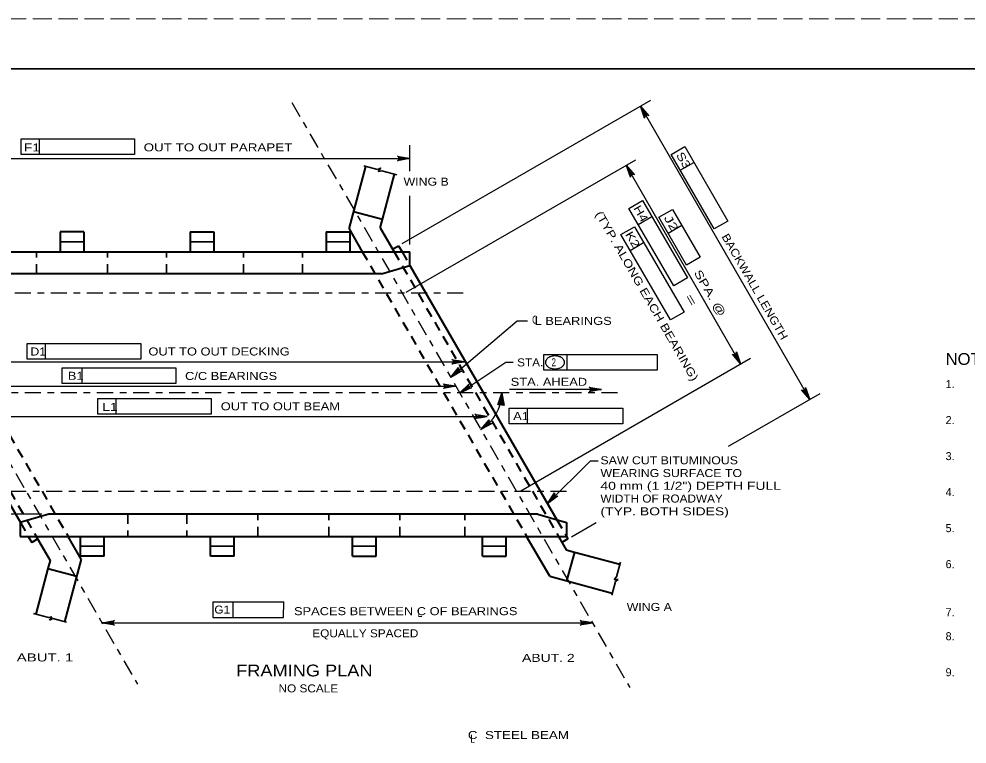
# Model space of a CAD drawing. Extents: x -11 to 79, y -154 to 0.
# Drawn here: x 43.06 to 57.27, y -10.87 to 0 of the extents above; entities that cross this region are included whole.
import ezdxf
from ezdxf.enums import TextEntityAlignment as Align

# ---------------------------------------------------------------- set-up
doc = ezdxf.new("R2010")
doc.units = 0
doc.header["$LTSCALE"] = 0.048
for name, pattern in [('DOT_DASHED', [7.7, 5, -1.2, 0.3, -1.2]), ('LONG_DASHED', [7.5, 6, -1.5]), ('MEDIUM_DASHED', [4.5, 3, -1.5])]:
    doc.linetypes.add(name, pattern=pattern)
for name, color, linetype, lineweight in [('1', 7, 'Continuous', 25), ('2', 7, 'Continuous', 35), ('3', 7, 'Continuous', 25), ('4', 7, 'Continuous', 25), ('63', 7, 'LONG_DASHED', 13)]:
    doc.layers.add(name, color=color, linetype=linetype, lineweight=lineweight)

msp = doc.modelspace()

# ---------------------------------------------------------------- hatches: boundary and pattern name
at = {"layer": '4'}
for points in [[(52.45392, -1.4), (52.41933, -1.42), (52.37667, -1.30608)], [(52.20325, -2.30208), (52.236, -2.28317), (52.163, -2.19442)], [(53.80583, -5.0805), (53.8385, -5.06167), (53.87883, -5.16933)], [(49.6225, -5.11992), (49.6225, -5.15767), (49.73583, -5.13883)], [(49.63117, -5.31317), (49.60675, -5.28433), (49.53242, -5.372)], [(49.77267, -5.55933), (49.75158, -5.528), (49.668, -5.60692)], [(54.87267, -5.58933), (54.838, -5.60933), (54.91533, -5.70325)], [(49.96292, -5.94175), (49.96292, -5.9795), (50.07633, -5.96067)], [(51.07808, -7.19333), (51.05158, -7.16642), (50.984, -7.25942)], [(44.428, -9.03375), (44.428, -9.07375), (44.308, -9.05375)], [(51.53808, -9.03375), (51.53808, -9.07375), (51.65808, -9.05375)]]:
    msp.add_hatch(color=256, dxfattribs=at).paths.add_polyline_path(points)

# ---------------------------------------------------------------- linework, layer by layer
at = {"layer": '1', "lineweight": 35}
msp.add_lwpolyline([(35.75, -21.25), (67.25, -21.25), (67.25, -0.75), (35.75, -0.75)], close=True, dxfattribs=at)
at = {"layer": '2', "lineweight": 40}
for p, q in [((48.00925, -3.14725), (48.26033, -2.21008)), ((48.50908, -3.00892), (48.69208, -2.32575)), ((48.50908, -3.00892), (48.07733, -2.89325)), ((48.47667, -3.13), (48.50908, -3.00892)), ((44.03225, -3.19375), (43.67792, -3.19375)), ((43.67792, -3.19375), (43.67792, -3.489)), ((44.03225, -3.19375), (44.03225, -3.489)), ((45.62758, -3.19375), (45.98192, -3.19375)), ((45.62758, -3.19375), (45.62758, -3.489)), ((45.98192, -3.19375), (45.98192, -3.489)), ((47.66542, -3.19375), (47.66542, -3.489)), ((47.66542, -3.19375), (48.01975, -3.19375)), ((48.00925, -3.14725), (48.20658, -3.489)), ((48.01975, -3.19375), (48.01975, -3.489)), ((48.47667, -3.13), (48.68392, -3.489)), ((48.66192, -3.45083), (48.75142, -3.39917)), ((48.75142, -3.39917), (48.80325, -3.489)), ((40.737, -3.489), (48.9225, -3.489)), ((40.88083, -3.73775), (43.08258, -7.55133)), ((48.49333, -3.82117), (41.16617, -3.82117)), ((48.9225, -3.69558), (51.1245, -7.50942)), ((50.83867, -7.42592), (43.51167, -7.42592)), ((43.0825, -7.75808), (51.26792, -7.75808)), ((43.20192, -7.75808), (43.25383, -7.84792)), ((43.34333, -7.79625), (43.25383, -7.84792)), ((43.32125, -7.75808), (43.52858, -8.11708)), ((43.99592, -8.09983), (43.79858, -7.75808)), ((43.9855, -8.05333), (43.9855, -7.75808)), ((44.33983, -8.05333), (44.33983, -7.75808)), ((45.93433, -8.05333), (45.93433, -7.75808)), ((46.28867, -8.05333), (46.28867, -7.75808)), ((48.062, -8.05333), (48.062, -7.75808)), ((48.41633, -8.05333), (48.41633, -7.75808)), ((50.01083, -8.05333), (50.01083, -7.75808)), ((50.36517, -8.05333), (50.36517, -7.75808)), ((51.0165, -8.356), (50.67133, -7.75808)), ((51.14867, -7.75808), (51.26517, -7.95983)), ((51.29008, -7.79625), (51.20058, -7.84792)), ((51.26792, -7.75792), (51.29008, -7.79625)), ((44.33983, -8.05333), (43.9855, -8.05333)), ((46.28867, -8.05333), (45.93433, -8.05333)), ((48.062, -8.05333), (48.41633, -8.05333)), ((50.01083, -8.05333), (50.36517, -8.05333)), ((51.38617, -7.99225), (52.06933, -8.17533)), ((43.49617, -8.23808), (43.31308, -8.92125)), ((43.52858, -8.11708), (43.49617, -8.23808)), ((43.49617, -8.23808), (43.92792, -8.35383)), ((43.99592, -8.09983), (43.74483, -9.037)), ((51.0165, -8.356), (51.95367, -8.60708))]:
    msp.add_line(p, q, dxfattribs=at)
at = {"layer": '2', "linetype": 'MEDIUM_DASHED', "lineweight": 40}
for p, q in [((40.8565, -3.489), (43.32125, -7.75808)), ((41.33392, -3.489), (43.79858, -7.75808)), ((48.20658, -3.489), (50.67133, -7.75808)), ((48.68392, -3.489), (51.14867, -7.75808)), ((48.80325, -3.489), (48.9225, -3.69558)), ((51.1245, -7.50942), (51.26792, -7.75792)), ((43.08258, -7.55133), (43.20192, -7.75808))]:
    msp.add_line(p, q, dxfattribs=at)
at = {"layer": '2', "lineweight": 40}
for points in [[(48.49333, -3.82117), (48.9225, -3.69567), (48.9225, -3.489)], [(43.51167, -7.42592), (43.0825, -7.55133), (43.0825, -7.75808)], [(50.83867, -7.42592), (51.26792, -7.55133), (51.26792, -7.75808)], [(51.26517, -7.95983), (51.38617, -7.99225), (51.2705, -8.424)]]:
    msp.add_lwpolyline(points, dxfattribs=at)
at = {"layer": '3', "linetype": 'DOT_DASHED'}
for p, q in [((39.77525, -1.20275), (44.83758, -9.971)), ((47.15383, -1.25217), (52.21617, -10.02042))]:
    msp.add_line(p, q, dxfattribs=at)
at = {"layer": '3', "lineweight": 35}
for p, q in [((48.43483, -2.25683), (48.22983, -2.20192)), ((48.7255, -2.33475), (48.5015, -2.27475)), ((44.03225, -3.34133), (43.67792, -3.34133)), ((45.62758, -3.34133), (45.98192, -3.34133)), ((47.66542, -3.34133), (48.01975, -3.34133)), ((44.33983, -7.90567), (43.9855, -7.90567)), ((46.28867, -7.90567), (45.93433, -7.90567)), ((48.062, -7.90567), (48.41633, -7.90567)), ((50.01083, -7.90567), (50.36517, -7.90567)), ((52.07833, -8.14192), (52.01825, -8.36592)), ((51.98267, -8.40483), (52.01825, -8.36592)), ((52.00042, -8.43258), (51.9455, -8.63758)), ((52.04242, -8.40125), (51.98267, -8.40483)), ((52.00042, -8.43258), (52.04242, -8.40125)), ((43.27975, -8.91233), (43.50375, -8.97233)), ((43.55517, -8.96092), (43.50375, -8.97233)), ((43.52217, -9.01092), (43.55517, -8.96092)), ((43.57042, -8.99025), (43.52217, -9.01092)), ((43.57042, -8.99025), (43.77542, -9.04517))]:
    msp.add_line(p, q, dxfattribs=at)
at = {"layer": '3', "linetype": 'MEDIUM_DASHED', "lineweight": 35}
for p, q in [((43.32317, -3.82117), (43.32317, -3.489)), ((44.387, -3.82117), (44.387, -3.489)), ((45.27283, -3.82117), (45.27283, -3.489)), ((46.42525, -3.82117), (46.42525, -3.489)), ((47.31108, -3.82117), (47.31108, -3.489)), ((44.69417, -7.42592), (44.69417, -7.75808)), ((45.58, -7.42592), (45.58, -7.75808)), ((46.64383, -7.75808), (46.64383, -7.44142)), ((47.70683, -7.75808), (47.70683, -7.42592)), ((48.77067, -7.75808), (48.77067, -7.42592)), ((49.74508, -7.75808), (49.74508, -7.42592))]:
    msp.add_line(p, q, dxfattribs=at)
at = {"layer": '3', "lineweight": 35}
msp.add_lwpolyline([(48.43483, -2.25683), (48.483, -2.23617), (48.45, -2.28608), (48.5015, -2.27475)], dxfattribs=at)
at = {"layer": '4'}
for p, q in [((48.8055, -3.36792), (52.5325, -1.21608)), ((52.37667, -1.30608), (54.91533, -5.70325)), ((43.09542, -1.79717), (44.79617, -1.79717)), ((43.09542, -2.03342), (43.09542, -1.79717)), ((43.371, -2.03342), (43.371, -1.79717)), ((44.79617, -1.79717), (44.79617, -2.03342)), ((48.9225, -2.27975), (48.9225, -1.89258)), ((52.83592, -2.02958), (53.04058, -1.9115)), ((53.04058, -1.9115), (53.68617, -3.03083)), ((40.737, -2.092), (48.9225, -2.092)), ((44.79617, -2.03342), (43.09542, -2.03342)), ((48.86525, -4.09833), (52.30967, -2.10975)), ((53.4815, -3.14883), (52.83592, -2.02958)), ((53.87883, -5.16933), (52.163, -2.19442)), ((52.97367, -2.26825), (53.17825, -2.15025)), ((48.9225, -3.38342), (48.9225, -2.653)), ((52.20258, -2.84117), (52.40717, -2.72308)), ((52.87692, -3.99942), (52.20258, -2.84117)), ((52.40717, -2.72308), (53.0815, -3.88133)), ((52.34125, -3.07933), (52.54542, -2.96042)), ((52.65275, -2.9725), (52.85733, -2.85442)), ((52.08167, -3.23367), (52.28633, -3.11567)), ((52.28633, -3.11567), (53.03242, -4.39375)), ((52.79042, -3.21117), (52.99508, -3.09317)), ((53.68617, -3.03083), (53.4815, -3.14883)), ((52.82783, -4.51175), (52.08167, -3.23367)), ((52.22067, -3.47167), (52.42467, -3.35258)), ((53.0815, -3.88133), (52.87692, -3.99942)), ((53.03242, -4.39375), (52.82783, -4.51175)), ((49.53242, -5.372), (50.53017, -4.52733)), ((50.53017, -4.52733), (50.68467, -4.52733)), ((43.18575, -4.8665), (44.88658, -4.8665)), ((43.18575, -5.10275), (43.18575, -4.8665)), ((43.46142, -5.10275), (43.46142, -4.8665)), ((44.88658, -4.8665), (44.88658, -5.10275)), ((44.88658, -5.10275), (43.18575, -5.10275)), ((50.58242, -7.0725), (54.02675, -5.08392)), ((50.92675, -5.26617), (50.92675, -5.03)), ((51.27658, -5.26617), (51.27658, -5.03)), ((41.68975, -5.13883), (49.73875, -5.13883)), ((43.711, -5.22825), (45.41183, -5.22825)), ((43.711, -5.4645), (43.711, -5.22825)), ((44.0085, -5.4645), (44.0085, -5.22825)), ((45.41183, -5.22825), (45.41183, -5.4645)), ((42.2595, -5.50558), (49.6095, -5.50558)), ((45.41183, -5.4645), (43.711, -5.4645)), ((51.794, -5.55367), (50.41233, -5.55367)), ((53.69617, -6.40708), (55.07117, -5.61325)), ((44.24283, -5.68833), (45.94358, -5.68833)), ((44.51842, -5.92458), (44.51842, -5.68833)), ((45.94358, -5.68833), (45.94358, -5.92458)), ((42.29683, -5.96067), (50.07917, -5.96067)), ((50.68633, -6.07092), (50.68633, -5.83467)), ((50.98158, -7.26183), (51.62825, -6.62558)), ((51.62825, -6.62558), (51.74167, -6.62558)), ((43.40608, -7.42592), (36.76125, -7.42592)), ((51.34417, -7.765), (51.7155, -7.55058)), ((45.96917, -8.73692), (45.96892, -8.97308)), ((45.96917, -8.73692), (47.0295, -8.73692)), ((46.27133, -8.97308), (46.27158, -8.73692)), ((47.02925, -8.97308), (47.0295, -8.73692)), ((44.308, -9.05375), (51.65808, -9.05375)), ((44.428, -9.05375), (51.65808, -9.05375)), ((45.96892, -8.97308), (47.02925, -8.97308))]:
    msp.add_line(p, q, dxfattribs=at)
at = {"layer": '4', "linetype": 'DOT_DASHED'}
for p, q in [((49.7185, -4.11175), (37.26075, -4.11175)), ((52.03158, -5.60692), (40.33992, -5.60692)), ((51.26867, -7.08592), (37.24933, -7.08592))]:
    msp.add_line(p, q, dxfattribs=at)
at = {"layer": '4'}
for points in [[(52.45392, -1.4), (52.41933, -1.42), (52.37667, -1.30608)], [(52.20325, -2.30208), (52.236, -2.28317), (52.163, -2.19442)], [(53.80583, -5.0805), (53.8385, -5.06167), (53.87883, -5.16933)], [(49.6225, -5.11992), (49.6225, -5.15767), (49.73583, -5.13883)], [(49.63117, -5.31317), (49.60675, -5.28433), (49.53242, -5.372)], [(49.77267, -5.55933), (49.75158, -5.528), (49.668, -5.60692)], [(54.87267, -5.58933), (54.838, -5.60933), (54.91533, -5.70325)], [(49.96292, -5.94175), (49.96292, -5.9795), (50.07633, -5.96067)], [(50.41075, -6.07092), (50.41075, -5.83467), (52.1115, -5.83467), (52.1115, -6.07092)], [(51.07808, -7.19333), (51.05158, -7.16642), (50.984, -7.25942)], [(44.428, -9.03375), (44.428, -9.07375), (44.308, -9.05375)], [(51.53808, -9.03375), (51.53808, -9.07375), (51.65808, -9.05375)]]:
    msp.add_lwpolyline(points, close=True, dxfattribs=at)
for points in [[(52.37667, -1.30608), (52.50017, -1.45008), (52.48433, -1.44258), (52.46983, -1.44242), (52.45792, -1.44683), (52.44817, -1.45492), (52.441, -1.46758), (52.43958, -1.485), (52.37667, -1.30608), (52.441, -1.46758), (52.44817, -1.45492), (52.37667, -1.30608), (52.45792, -1.44683), (52.46983, -1.44242), (52.37667, -1.30608), (52.48433, -1.44258)], [(48.9225, -2.092), (48.73608, -2.12692), (48.75042, -2.117), (48.75783, -2.1045), (48.76, -2.092), (48.75783, -2.0795), (48.75042, -2.067), (48.73608, -2.05708), (48.9225, -2.092), (48.75042, -2.067), (48.75783, -2.0795), (48.9225, -2.092), (48.76, -2.092), (48.75783, -2.1045), (48.9225, -2.092), (48.75042, -2.117)], [(52.163, -2.19442), (52.28642, -2.33842), (52.27058, -2.331), (52.25608, -2.33083), (52.24417, -2.33517), (52.23442, -2.34325), (52.22733, -2.35592), (52.22583, -2.37333), (52.163, -2.19442), (52.22733, -2.35592), (52.23442, -2.34325), (52.163, -2.19442), (52.24417, -2.33517), (52.25608, -2.33083), (52.163, -2.19442), (52.27058, -2.331)], [(52.85733, -2.85442), (53.2715, -3.5725), (53.06692, -3.6905), (52.65275, -2.9725)], [(49.73875, -5.13883), (49.55233, -5.17375), (49.56667, -5.16383), (49.57408, -5.15133), (49.57625, -5.13883), (49.57408, -5.12633), (49.56667, -5.11383), (49.55233, -5.10392), (49.73875, -5.13883), (49.56667, -5.11383), (49.57408, -5.12633), (49.73875, -5.13883), (49.57625, -5.13883), (49.57408, -5.15133), (49.73875, -5.13883), (49.56667, -5.16383)], [(50.92675, -5.03), (52.6275, -5.03), (52.6275, -5.26617), (50.92675, -5.26617)], [(53.87883, -5.16933), (53.75542, -5.02533), (53.77125, -5.03275), (53.78575, -5.03292), (53.79767, -5.02858), (53.80742, -5.0205), (53.8145, -5.00783), (53.816, -4.99042), (53.87883, -5.16933), (53.8145, -5.00783), (53.80742, -5.0205), (53.87883, -5.16933), (53.79767, -5.02858), (53.78575, -5.03292), (53.87883, -5.16933), (53.77125, -5.03275)], [(49.53242, -5.372), (49.65208, -5.22492), (49.64758, -5.24175), (49.65, -5.25608), (49.65642, -5.267), (49.66617, -5.27517), (49.67992, -5.27992), (49.69725, -5.27825), (49.53242, -5.372), (49.67992, -5.27992), (49.66617, -5.27517), (49.53242, -5.372), (49.65642, -5.267), (49.65, -5.25608), (49.53242, -5.372), (49.64758, -5.24175)], [(49.668, -5.60692), (50.35725, -5.14383), (50.47067, -5.14383)], [(49.6095, -5.50558), (49.42308, -5.5405), (49.43742, -5.53058), (49.44483, -5.51808), (49.447, -5.50558), (49.44483, -5.49308), (49.43742, -5.48058), (49.42308, -5.47067), (49.6095, -5.50558), (49.43742, -5.48058), (49.44483, -5.49308), (49.6095, -5.50558), (49.447, -5.50558), (49.44483, -5.51808), (49.6095, -5.50558), (49.43742, -5.53058)], [(49.668, -5.60692), (49.80325, -5.47392), (49.79683, -5.49025), (49.79767, -5.50475), (49.80292, -5.51633), (49.81167, -5.5255), (49.82475, -5.53175), (49.84225, -5.532), (49.668, -5.60692), (49.82475, -5.53175), (49.81167, -5.5255), (49.668, -5.60692), (49.80292, -5.51633), (49.79767, -5.50475), (49.668, -5.60692), (49.79683, -5.49025)], [(51.794, -5.55367), (51.60758, -5.58858), (51.62192, -5.57867), (51.62933, -5.56617), (51.6315, -5.55367), (51.62933, -5.54117), (51.62192, -5.52867), (51.60758, -5.51875), (51.794, -5.55367), (51.62192, -5.52867), (51.62933, -5.54117), (51.794, -5.55367), (51.6315, -5.55367), (51.62933, -5.56617), (51.794, -5.55367), (51.62192, -5.57867)], [(54.91533, -5.70325), (54.79183, -5.55925), (54.80767, -5.56675), (54.82217, -5.56692), (54.83408, -5.5625), (54.84383, -5.55442), (54.851, -5.54175), (54.85242, -5.52433), (54.91533, -5.70325), (54.851, -5.54175), (54.84383, -5.55442), (54.91533, -5.70325), (54.83408, -5.5625), (54.82217, -5.56692), (54.91533, -5.70325), (54.80767, -5.56675)], [(50.29875, -5.60658), (50.30733, -5.796), (50.29942, -5.78042), (50.28808, -5.77133), (50.276, -5.76742), (50.26333, -5.76783), (50.24992, -5.77342), (50.23808, -5.78625), (50.29875, -5.60658), (50.24992, -5.77342), (50.26333, -5.76783), (50.29875, -5.60658), (50.276, -5.76742), (50.28808, -5.77133), (50.29875, -5.60658), (50.29942, -5.78042)], [(50.29875, -5.60692), (50.33367, -5.79333), (50.32367, -5.779), (50.31117, -5.77158), (50.29867, -5.76942), (50.28617, -5.77158), (50.27367, -5.779), (50.26375, -5.79333), (50.29875, -5.60692), (50.27367, -5.779), (50.28617, -5.77158), (50.29875, -5.60692), (50.29867, -5.76942), (50.31117, -5.77158), (50.29875, -5.60692), (50.32367, -5.779)], [(45.94358, -5.92458), (44.24283, -5.92458), (44.24283, -5.68833)], [(50.07917, -5.96067), (49.89275, -5.99558), (49.90708, -5.98567), (49.9145, -5.97317), (49.91667, -5.96067), (49.9145, -5.94817), (49.90708, -5.93567), (49.89275, -5.92575), (50.07917, -5.96067), (49.90708, -5.93567), (49.9145, -5.94817), (50.07917, -5.96067), (49.91667, -5.96067), (49.9145, -5.97317), (50.07917, -5.96067), (49.90708, -5.98567)], [(49.98383, -6.15392), (50.109, -6.01142), (50.10383, -6.02817), (50.10567, -6.0425), (50.11175, -6.05367), (50.12108, -6.06225), (50.13467, -6.0675), (50.15208, -6.0665), (49.98383, -6.15392), (50.13467, -6.0675), (50.12108, -6.06225), (49.98383, -6.15392), (50.11175, -6.05367), (50.10567, -6.0425), (49.98383, -6.15392), (50.10383, -6.02817)], [(50.98158, -7.26183), (51.08992, -7.10617), (51.08667, -7.12333), (51.09017, -7.13742), (51.09742, -7.14783), (51.10775, -7.15525), (51.12175, -7.159), (51.139, -7.156), (50.98158, -7.26183), (51.12175, -7.159), (51.10775, -7.15525), (50.98158, -7.26183), (51.09742, -7.14783), (51.09017, -7.13742), (50.98158, -7.26183), (51.08667, -7.12333)], [(44.308, -9.05375), (44.49442, -9.01883), (44.48008, -9.02875), (44.47267, -9.04125), (44.4705, -9.05375), (44.47267, -9.06625), (44.48008, -9.07875), (44.49442, -9.08867), (44.308, -9.05375), (44.48008, -9.07875), (44.47267, -9.06625), (44.308, -9.05375), (44.4705, -9.05375), (44.47267, -9.04125), (44.308, -9.05375), (44.48008, -9.02875)], [(51.65808, -9.05375), (51.47167, -9.08867), (51.486, -9.07875), (51.49342, -9.06625), (51.49558, -9.05375), (51.49342, -9.04125), (51.486, -9.02875), (51.47167, -9.01883), (51.65808, -9.05375), (51.486, -9.02875), (51.49342, -9.04125), (51.65808, -9.05375), (51.49558, -9.05375), (51.49342, -9.06625), (51.65808, -9.05375), (51.486, -9.07875)]]:
    msp.add_lwpolyline(points, dxfattribs=at)
for centre, radius, start, end in [((51.01979, -5.14857), 0.06702, 148.55069, 180), ((51.05634, -5.17092), 0.10986, 124.10897, 148.55069), ((51.08033, -5.20633), 0.15263, 105.67084, 124.10897), ((51.09604, -5.26233), 0.2108, 90, 105.67084), ((51.09604, -5.26233), 0.2108, 74.32916, 90), ((51.11175, -5.20633), 0.15263, 55.89103, 74.32916), ((51.13573, -5.17092), 0.10986, 31.44931, 55.89103), ((51.17228, -5.14857), 0.06702, 0, 31.44931), ((51.01979, -5.14857), 0.06702, 180, 211.44931), ((51.05634, -5.12622), 0.10986, 211.44931, 235.89103), ((51.08033, -5.0908), 0.15263, 235.89103, 254.32916), ((51.09604, -5.0348), 0.2108, 254.32916, 270), ((51.09604, -5.0348), 0.2108, 270, 285.67084), ((51.11175, -5.0908), 0.15263, 285.67084, 304.10897), ((51.13573, -5.12622), 0.10986, 304.10897, 328.55069), ((51.17228, -5.14857), 0.06702, 328.55069, 0), ((49.66799, -5.60686), 0.6307, 300.0002, 359.99746)]:
    msp.add_arc(centre, radius, start, end, dxfattribs=at)
at = {"layer": '63'}
msp.add_lwpolyline([(34, -22), (68, -22), (68, 0), (34, 0)], close=True, dxfattribs=at)

# ---------------------------------------------------------------- texts
at = {"layer": '4'}
for s, height, width, p in [('F1', 0.12, 1.3, (43.25587, -1.98683)), ('OUT TO OUT PARAPET ', 0.12, 1.25, (46.07346, -1.98508)), ('D1', 0.12, 1.15, (43.35129, -5.0455)), ('OUT TO OUT DECKING', 0.12, 1.2, (46.06162, -5.04525)), ('C/C BEARINGS', 0.12, 1.2, (46.2415, -5.41208)), ('L1', 0.12, 1.3, (44.42604, -5.87533)), ('OUT TO OUT BEAM', 0.12, 1.2, (46.98013, -5.86717)), ('A1', 0.12, 1.2, (50.58746, -6.01367)), ('SPACES BETWEEN C OF BEARINGS', 0.12, 1.2, (48.85846, -8.93842)), ('L', 0.12, 0.75, (49.07171, -8.96408)), ('EQUALLY SPACED', 0.12, 1.1, (48.2535, -9.2705)), ('FRAMING PLAN', 0.1772, 1.15, (47.33937, -9.85658))]:
    msp.add_text(s, height=height, dxfattribs=dict(at, width=width)).set_placement(p, align=Align.CENTER)
for s, rotation, width, p in [('S3', 299.975, 1.3, (52.97019, -2.14773)), ('H4', 300.208, 1.25, (52.33106, -2.9481)), ('J2', 299.975, 1.5, (52.78727, -3.09115)), ('K2', 300.276, 1.3, (52.20914, -3.3385)), ('G1', 359.938, 1.1, (46.1086, -8.91496))]:
    msp.add_text(s, height=0.12, rotation=rotation, dxfattribs=dict(at, width=width)).set_placement(p, align=Align.CENTER)
for s, height, width, p in [('WING B', 0.12, 1.15, (48.82675, -2.49908)), ('C', 0.12, 0.65, (50.75433, -4.56808)), ('L BEARINGS', 0.12, 1.2, (50.79058, -4.58675)), ('STA.', 0.12, 1.1, (50.52817, -5.209)), ('2', 0.12, 0.75, (51.04408, -5.20675)), ('NOTES:', 0.1772, 1.05, (56.9505, -5.18617)), ('B1', 0.12, 1.2, (43.79483, -5.4095)), ('STA. AHEAD', 0.12, 1.2, (50.43258, -5.50008)), ('SAW CUT BITUMINOUS', 0.12, 1.15, (51.7775, -6.67658)), ('WEARING SURFACE TO', 0.12, 1.15, (51.7775, -6.86783)), ('40 mm (1 1/2") DEPTH FULL', 0.12, 1.3, (51.7775, -7.05908)), ('WIDTH OF ROADWAY', 0.12, 1.1, (51.7775, -7.25025)), ('(TYP. BOTH SIDES)', 0.12, 1.3, (51.7775, -7.4415)), ('WING A', 0.12, 1.15, (52.17133, -8.87517)), ('ABUT. 1', 0.12, 1.4, (43.02825, -9.632)), ('ABUT. 2', 0.12, 1.3, (50.60283, -9.63875)), ('NO SCALE', 0.12, 1.1, (46.95267, -10.09633)), ('C  STEEL BEAM', 0.12, 1.25, (49.78958, -10.79542)), ('L', 0.12, 0.75, (49.82892, -10.85183))]:
    msp.add_text(s, height=height, dxfattribs=dict(at, width=width)).set_placement(p)
for s, width, p in [('(TYP. ALONG EACH BEARING)', 1.25, (51.69542, -2.92333)), ('BACKWALL LENGTH', 1.15, (53.58817, -3.26217)), ('SPA. @', 1.35, (53.17358, -3.80392)), ('= ', 1.9, (53.03917, -4.16525))]:
    msp.add_text(s, height=0.12, rotation=299.975, dxfattribs=dict(at, width=width)).set_placement(p)
for s, p in [('1.', (56.9505, -5.53375)), ('2.', (56.9505, -6.07375)), ('3.', (56.9505, -6.61375)), ('4.', (56.9505, -7.15375)), ('5.', (56.9505, -7.69375)), ('6.', (56.9505, -8.23375)), ('7.', (56.9505, -8.95375)), ('8.', (56.9505, -9.31375)), ('9.', (56.9505, -9.85375))]:
    msp.add_text(s, height=0.12, dxfattribs=at).set_placement(p)

doc.saveas('drawing.dxf')
